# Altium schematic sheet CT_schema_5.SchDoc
size 274 x 160 mm
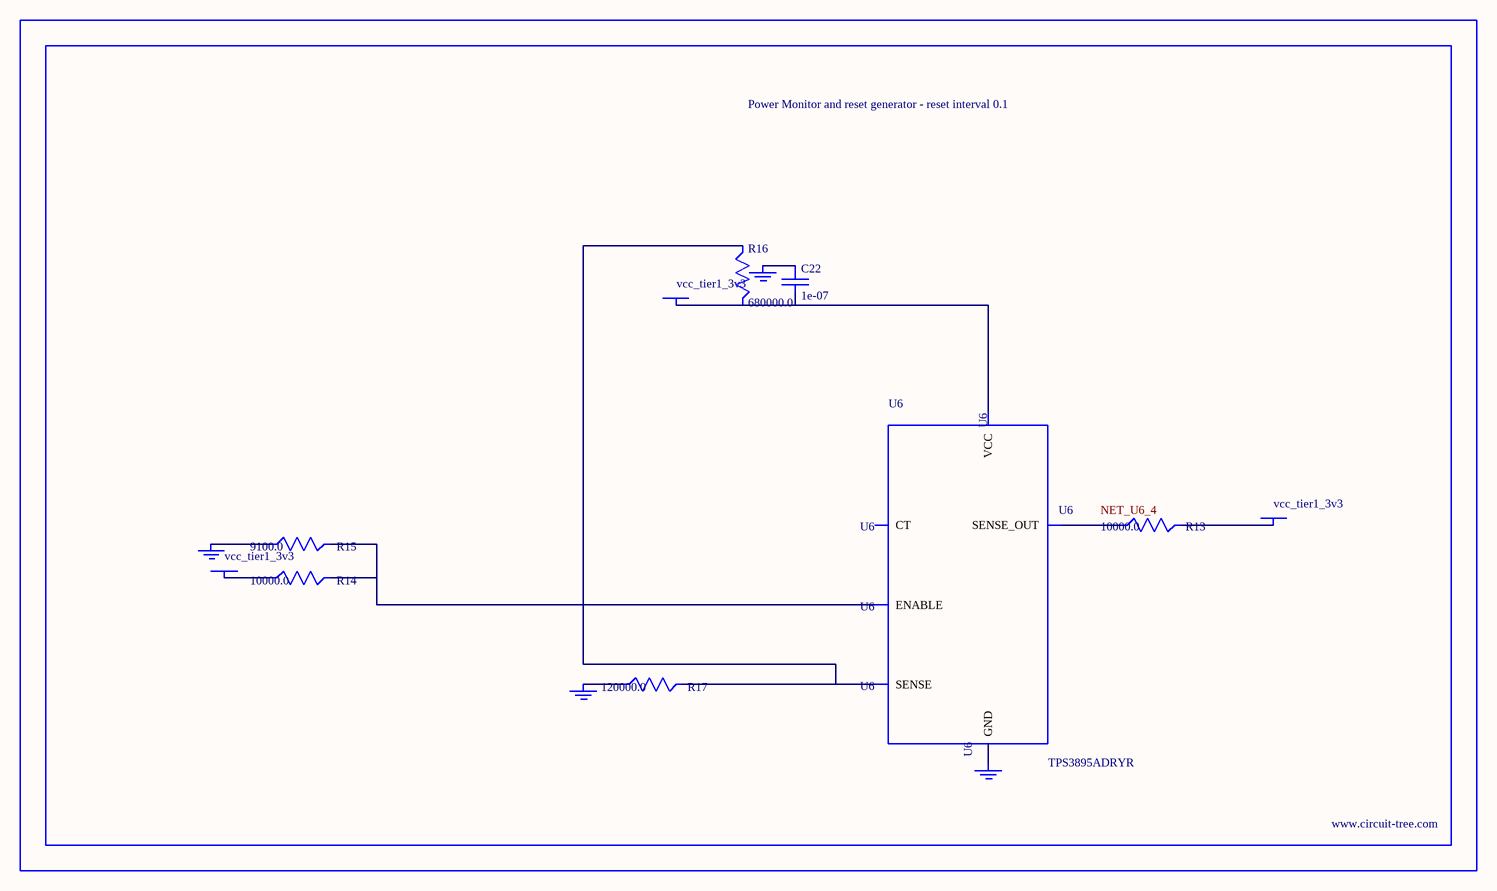
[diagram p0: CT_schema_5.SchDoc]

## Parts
BORDER4  (no value)
C22  1e-07  [C0402]
GND_INSTANCE_4_0  (no value)
GND_INSTANCE_4_1  (no value)
GND_INSTANCE_4_2  (no value)
GND_INSTANCE_4_3  (no value)
POWER_INSTANCE_4_0  vcc_tier1_3v3
POWER_INSTANCE_4_1  vcc_tier1_3v3
POWER_INSTANCE_4_2  vcc_tier1_3v3
R13  10000.0  [R0603]
R14  10000.0  [R0603]
R15  9100.0  [R0603]
R16  680000.0  [R0603]
R17  120000.0  [R0603]
U6  TPS3895ADRYR  [SON-6]

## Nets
NetC22_1: C22.1 GND_INSTANCE_4_2.0(GND)
NetC22_2: C22.2 POWER_INSTANCE_4_2.0(PWR) R16.2 U6.6(VCC)
NetGND_INSTANCE_4_0_0: GND_INSTANCE_4_0.0(GND) R15.1
NetGND_INSTANCE_4_1_0: GND_INSTANCE_4_1.0(GND) R17.1
NetGND_INSTANCE_4_3_0: GND_INSTANCE_4_3.0(GND) U6.2(GND)
NetPOWER_INSTANCE_4_0_0: POWER_INSTANCE_4_0.0(PWR) R14.1
NetPOWER_INSTANCE_4_1_0: POWER_INSTANCE_4_1.0(PWR) R13.2
NetR13_1: R13.1 U6.4(SENSE_OUT)
NetR14_2: R14.2 R15.2 U6.1(ENABLE)
NetR16_1: R16.1 R17.2 U6.3(SENSE)

Not connected (* = marked no-connect by the designer): U6 5(CT)

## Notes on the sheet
- Labels drawn without touching a wire or pin: NET_U6_4

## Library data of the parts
BORDER4 = BORDER_PAGE4
C22 = C0402C104K3RACTU
GND_INSTANCE_4_0-GND_INSTANCE_4_3 = GND
POWER_INSTANCE_4_0-POWER_INSTANCE_4_2 = PWR
R13 R14 = RC0603JR-0710KL
R15 = RC0603JR-079K1L
R16 = RC0603JR-07680KL
R17 = RC0603JR-07120KL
